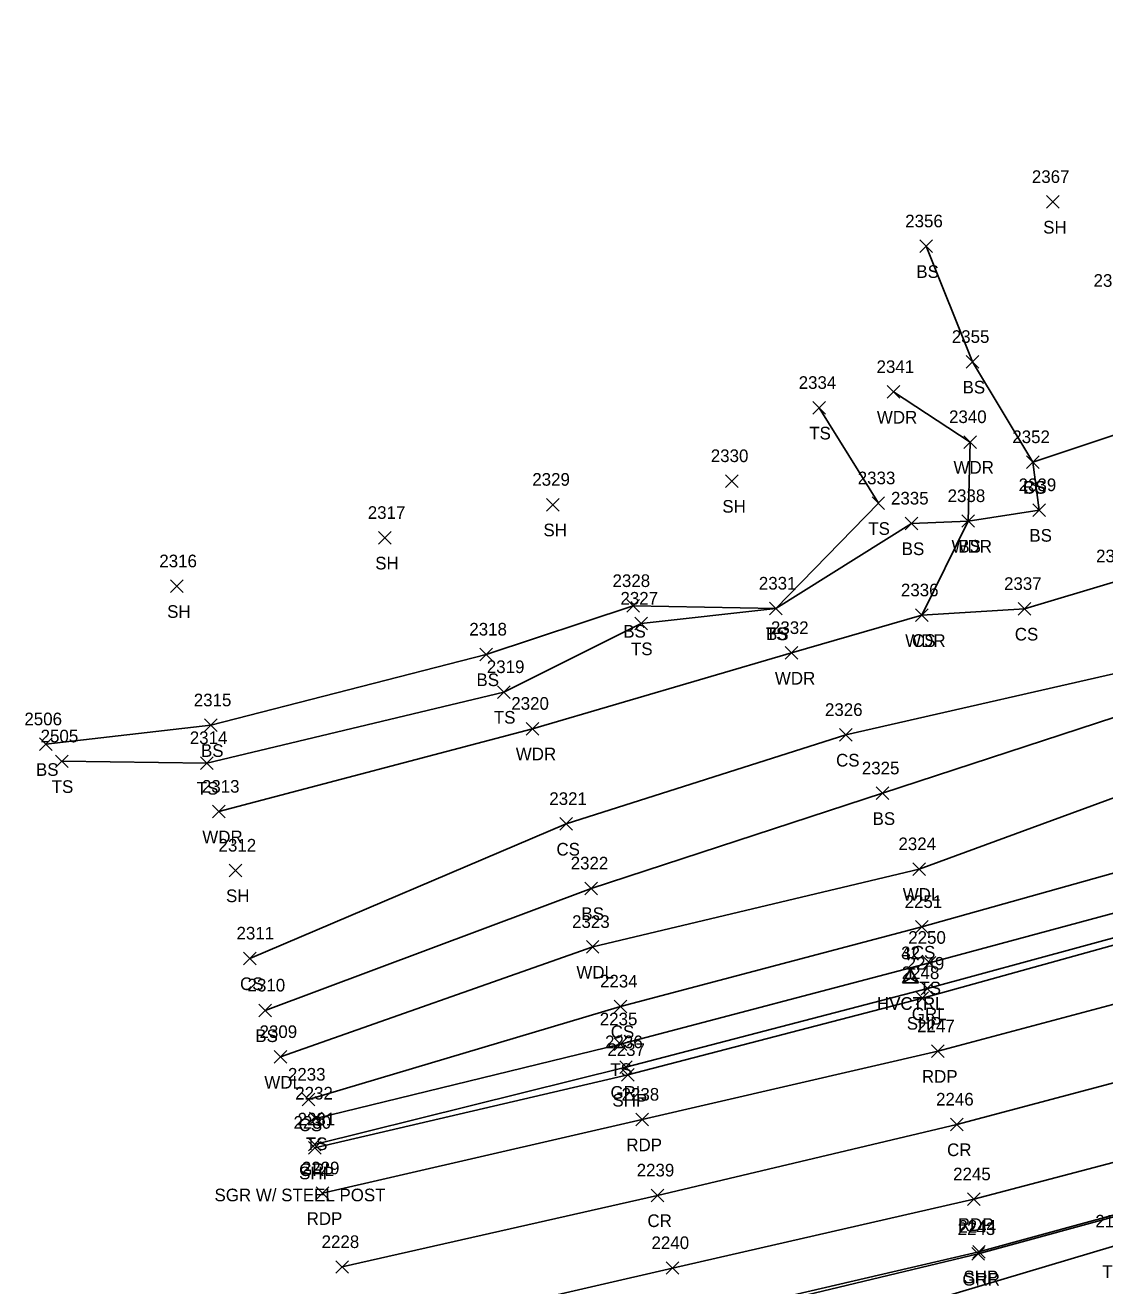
# Model space of a CAD drawing. Extents: x 1502194 to 1507887, y 142265 to 144150.
# Drawn here: x 1506482.3 to 1506653.1, y 143449.6 to 143648.9 of the extents above; entities that cross this region are included whole.
import ezdxf

# ---------------------------------------------------------------- set-up
doc = ezdxf.new("R2010")
doc.units = 0
for name, color, linetype in [('C_A', 7, 'Continuous'), ('C_I', 7, 'Continuous'), ('CPSM', 7, 'Continuous'), ('L_A', 7, 'Continuous'), ('L_I', 7, 'Continuous'), ('L_TIC', 7, 'Continuous'), ('LAWA', 7, 'Continuous'), ('LELB', 7, 'Continuous'), ('P_A', 7, 'Continuous'), ('P_I', 7, 'Continuous'), ('P_TIC', 7, 'Continuous'), ('PET', 7, 'Continuous'), ('PRC', 7, 'Continuous'), ('PSP', 7, 'Continuous'), ('R_A', 7, 'Continuous'), ('R_C', 7, 'Continuous'), ('R_I', 7, 'Continuous'), ('R_TIC', 7, 'Continuous'), ('RGR', 7, 'Continuous')]:
    doc.layers.add(name, color=color, linetype=linetype)

msp = doc.modelspace()

# ---------------------------------------------------------------- linework, layer by layer
at = {"layer": 'CPSM'}
for p, q in [((1506621.06, 143497.5), (1506622.31, 143499.66)), ((1506621.06, 143497.5), (1506622.31, 143498.22)), ((1506621.07, 143497.49), (1506622.32, 143499.66)), ((1506621.07, 143497.49), (1506622.32, 143498.21)), ((1506623.56, 143497.5), (1506622.31, 143499.66)), ((1506622.31, 143498.22), (1506622.31, 143499.66)), ((1506622.31, 143498.22), (1506622.31, 143498.22)), ((1506622.31, 143498.22), (1506623.56, 143497.5)), ((1506623.57, 143497.49), (1506622.32, 143499.66)), ((1506622.32, 143498.21), (1506622.32, 143499.66)), ((1506622.32, 143498.21), (1506622.32, 143498.21)), ((1506622.32, 143498.21), (1506623.57, 143497.49)), ((1506621.06, 143497.5), (1506623.56, 143497.5)), ((1506621.07, 143497.49), (1506623.57, 143497.49))]:
    msp.add_line(p, q, dxfattribs=at)
at = {"layer": 'L_TIC'}
for points in [[(1506643.82, 143620), (1506645.82, 143622)], [(1506645.82, 143620), (1506643.82, 143622)], [(1506623.81, 143612.98), (1506625.81, 143614.98)], [(1506625.81, 143612.98), (1506623.81, 143614.98)], [(1506631.12, 143594.7), (1506633.12, 143596.7)], [(1506633.12, 143594.7), (1506631.12, 143596.7)], [(1506618.65, 143589.94), (1506620.65, 143591.94)], [(1506620.65, 143589.94), (1506618.65, 143591.94)], [(1506606.9, 143587.43), (1506608.9, 143589.43)], [(1506608.9, 143587.43), (1506606.9, 143589.43)], [(1506630.77, 143582.02), (1506632.77, 143584.02)], [(1506632.77, 143582.02), (1506630.77, 143584.02)], [(1506640.69, 143578.85), (1506642.69, 143580.85)], [(1506642.69, 143578.85), (1506640.69, 143580.85)], [(1506640.69, 143578.85), (1506642.69, 143580.85)], [(1506642.69, 143578.85), (1506640.69, 143580.85)], [(1506593.09, 143575.85), (1506595.09, 143577.85)], [(1506595.09, 143575.85), (1506593.09, 143577.85)], [(1506564.78, 143572.11), (1506566.78, 143574.11)], [(1506566.78, 143572.11), (1506564.78, 143574.11)], [(1506616.24, 143572.34), (1506618.24, 143574.34)], [(1506618.24, 143572.34), (1506616.24, 143574.34)], [(1506630.46, 143569.53), (1506632.46, 143571.53)], [(1506632.46, 143569.53), (1506630.46, 143571.53)], [(1506630.46, 143569.53), (1506632.46, 143571.53)], [(1506632.46, 143569.53), (1506630.46, 143571.53)], [(1506641.69, 143571.26), (1506643.69, 143573.26)], [(1506643.69, 143571.26), (1506641.69, 143573.26)], [(1506621.5, 143569.14), (1506623.5, 143571.14)], [(1506623.5, 143569.14), (1506621.5, 143571.14)], [(1506538.18, 143566.87), (1506540.18, 143568.87)], [(1506540.18, 143566.87), (1506538.18, 143568.87)], [(1506505.27, 143559.21), (1506507.27, 143561.21)], [(1506507.27, 143559.21), (1506505.27, 143561.21)], [(1506577.46, 143556.09), (1506579.46, 143558.09)], [(1506579.46, 143556.09), (1506577.46, 143558.09)], [(1506600.03, 143555.69), (1506602.03, 143557.69)], [(1506602.03, 143555.69), (1506600.03, 143557.69)], [(1506600.03, 143555.69), (1506602.03, 143557.69)], [(1506602.03, 143555.69), (1506600.03, 143557.69)], [(1506639.38, 143555.63), (1506641.38, 143557.63)], [(1506641.38, 143555.63), (1506639.38, 143557.63)], [(1506623.13, 143554.62), (1506625.13, 143556.62)], [(1506625.13, 143554.62), (1506623.13, 143556.62)], [(1506623.13, 143554.62), (1506625.13, 143556.62)], [(1506625.13, 143554.62), (1506623.13, 143556.62)], [(1506578.71, 143553.31), (1506580.71, 143555.31)], [(1506580.71, 143553.31), (1506578.71, 143555.31)], [(1506554.24, 143548.42), (1506556.24, 143550.42)], [(1506556.24, 143548.42), (1506554.24, 143550.42)], [(1506602.52, 143548.66), (1506604.52, 143550.66)], [(1506604.52, 143548.66), (1506602.52, 143550.66)], [(1506557.02, 143542.48), (1506559.02, 143544.48)], [(1506559.02, 143542.48), (1506557.02, 143544.48)], [(1506510.67, 143537.22), (1506512.67, 143539.22)], [(1506512.67, 143537.22), (1506510.67, 143539.22)], [(1506561.54, 143536.68), (1506563.54, 143538.68)], [(1506563.54, 143536.68), (1506561.54, 143538.68)], [(1506611.11, 143535.7), (1506613.11, 143537.7)], [(1506613.11, 143535.7), (1506611.11, 143537.7)], [(1506484.57, 143534.22), (1506486.57, 143536.22)], [(1506486.57, 143534.22), (1506484.57, 143536.22)], [(1506487.09, 143531.52), (1506489.09, 143533.52)], [(1506489.09, 143531.52), (1506487.09, 143533.52)], [(1506510.03, 143531.25), (1506512.03, 143533.25)], [(1506512.03, 143531.25), (1506510.03, 143533.25)], [(1506616.89, 143526.46), (1506618.89, 143528.46)], [(1506618.89, 143526.46), (1506616.89, 143528.46)], [(1506511.95, 143523.56), (1506513.95, 143525.56)], [(1506513.95, 143523.56), (1506511.95, 143525.56)], [(1506566.89, 143521.62), (1506568.89, 143523.62)], [(1506568.89, 143521.62), (1506566.89, 143523.62)], [(1506514.58, 143514.25), (1506516.58, 143516.25)], [(1506516.58, 143514.25), (1506514.58, 143516.25)], [(1506622.68, 143514.47), (1506624.68, 143516.47)], [(1506624.68, 143514.47), (1506622.68, 143516.47)], [(1506570.84, 143511.42), (1506572.84, 143513.42)], [(1506572.84, 143511.42), (1506570.84, 143513.42)], [(1506623.1, 143505.32), (1506625.1, 143507.32)], [(1506625.1, 143505.32), (1506623.1, 143507.32)], [(1506571.06, 143502.17), (1506573.06, 143504.17)], [(1506573.06, 143502.17), (1506571.06, 143504.17)], [(1506516.85, 143500.34), (1506518.85, 143502.34)], [(1506518.85, 143500.34), (1506516.85, 143502.34)], [(1506624.32, 143499.66), (1506626.32, 143501.66)], [(1506626.32, 143499.66), (1506624.32, 143501.66)], [(1506519.26, 143492.12), (1506521.26, 143494.12)], [(1506521.26, 143492.12), (1506519.26, 143494.12)], [(1506575.48, 143492.75), (1506577.48, 143494.75)], [(1506577.48, 143492.75), (1506575.48, 143494.75)], [(1506575.44, 143486.76), (1506577.44, 143488.76)], [(1506577.44, 143486.76), (1506575.44, 143488.76)], [(1506521.71, 143484.76), (1506523.71, 143486.76)], [(1506523.71, 143484.76), (1506521.71, 143486.76)], [(1506526.12, 143478.02), (1506528.12, 143480.02)], [(1506528.12, 143478.02), (1506526.12, 143480.02)], [(1506527.28, 143475.03), (1506529.28, 143477.03)], [(1506529.28, 143475.03), (1506527.28, 143477.03)]]:
    msp.add_lwpolyline(points, dxfattribs=at)
at = {"layer": 'LAWA'}
for points in [[(1506522.71, 143485.76), (1506572.06, 143503.17), (1506623.68, 143515.47), (1506667.22, 143531.44), (1506692.19, 143539.75), (1506705.6, 143543.12), (1506724.44, 143544.97), (1506738.66, 143547.16), (1506749.81, 143546.64), (1506758.77, 143557.3), (1506807.57, 143579.94), (1506846.79, 143592.4), (1506896.99, 143614.38)], [(1506512.95, 143524.56), (1506562.54, 143537.68), (1506603.52, 143549.66), (1506624.13, 143555.62), (1506631.46, 143570.53), (1506631.77, 143583.02), (1506619.65, 143590.94)]]:
    msp.add_lwpolyline(points, dxfattribs=at)
at = {"layer": 'LELB'}
for points in [[(1506624.13, 143555.62), (1506640.38, 143556.63), (1506654.94, 143561), (1506672.72, 143565.79), (1506679.72, 143575.67), (1506695.05, 143577.62), (1506699.47, 143577.91), (1506701.5, 143575.19), (1506703.76, 143575.39), (1506707.13, 143577.97), (1506705.55, 143581.26), (1506716.61, 143587.23), (1506735.68, 143602.47), (1506756.62, 143603.39), (1506780.29, 143609.03), (1506830.83, 143625.99), (1506880.34, 143648.95)], [(1506517.85, 143501.34), (1506567.89, 143522.62), (1506612.11, 143536.7), (1506661.61, 143547.98), (1506681.76, 143559.52), (1506695.53, 143572.24), (1506704.85, 143572.91), (1506725.52, 143573.91), (1506746.5, 143587.18), (1506797.75, 143604.14), (1506837.79, 143614.31), (1506888.27, 143631.28)], [(1506511.67, 143538.22), (1506555.24, 143549.42), (1506578.46, 143557.09), (1506601.03, 143556.69), (1506622.5, 143570.14), (1506631.46, 143570.53), (1506642.69, 143572.26), (1506641.69, 143579.85), (1506632.12, 143595.7), (1506624.81, 143613.98)], [(1506520.26, 143493.12), (1506571.84, 143512.42), (1506617.89, 143527.46), (1506663.2, 143542.3), (1506684.6, 143550.02), (1506709.64, 143561.03), (1506743.74, 143569.88), (1506756.3, 143575.97), (1506802.67, 143594.79), (1506845.42, 143601.65), (1506896.99, 143614.38)], [(1506527.12, 143479.02), (1506576.48, 143493.75), (1506624.1, 143506.32), (1506671.3, 143519.58), (1506718.08, 143535.11), (1506766.47, 143551.82), (1506810.91, 143567.85), (1506852.21, 143584.27), (1506899, 143603.69)], [(1506528.28, 143476.03), (1506576.44, 143487.76), (1506625.32, 143500.66), (1506672.84, 143513.46), (1506720.65, 143528.12), (1506770.21, 143545.68), (1506814.12, 143560.53), (1506853.98, 143576.57), (1506901.25, 143597.01)], [(1506511.03, 143532.25), (1506558.02, 143543.48), (1506579.71, 143554.31), (1506601.03, 143556.69), (1506617.24, 143573.34), (1506607.9, 143588.43)], [(1506641.69, 143579.85), (1506662.54, 143586.81), (1506690.86, 143582.96)], [(1506920.49, 143550.15), (1506879.81, 143532.73), (1506832.93, 143512.84), (1506791.89, 143498.35), (1506750.34, 143484.06), (1506703.75, 143467.85), (1506654.25, 143455.79), (1506605.88, 143441.31), (1506565.5, 143431.73), (1506554.53, 143418.24), (1506550.8, 143411.14), (1506553.36, 143401.15), (1506568.06, 143393.58), (1506589.98, 143377.59)], [(1506485.57, 143535.22), (1506511.67, 143538.22)], [(1506488.09, 143532.52), (1506511.03, 143532.25)]]:
    msp.add_lwpolyline(points, dxfattribs=at)
at = {"layer": 'P_TIC'}
for points in [[(1506623.2, 143494.08), (1506625.2, 143496.08)], [(1506625.2, 143494.08), (1506623.2, 143496.08)], [(1506625.64, 143485.68), (1506627.64, 143487.68)], [(1506627.64, 143485.68), (1506625.64, 143487.68)], [(1506576.64, 143481.92), (1506578.64, 143483.92)], [(1506578.64, 143481.92), (1506576.64, 143483.92)], [(1506578.89, 143474.85), (1506580.89, 143476.85)], [(1506580.89, 143474.85), (1506578.89, 143476.85)], [(1506628.68, 143474.08), (1506630.68, 143476.08)], [(1506630.68, 143474.08), (1506628.68, 143476.08)], [(1506527.1, 143470.41), (1506529.1, 143472.41)], [(1506529.1, 143470.41), (1506527.1, 143472.41)], [(1506528.33, 143463.2), (1506530.33, 143465.2)], [(1506530.33, 143463.2), (1506528.33, 143465.2)], [(1506581.29, 143462.86), (1506583.29, 143464.86)], [(1506583.29, 143462.86), (1506581.29, 143464.86)], [(1506631.33, 143462.25), (1506633.33, 143464.25)], [(1506633.33, 143462.25), (1506631.33, 143464.25)], [(1506632.16, 143453.96), (1506634.16, 143455.96)], [(1506634.16, 143453.96), (1506632.16, 143455.96)], [(1506531.45, 143451.54), (1506533.45, 143453.54)], [(1506533.45, 143451.54), (1506531.45, 143453.54)], [(1506583.71, 143451.38), (1506585.71, 143453.38)], [(1506585.71, 143451.38), (1506583.71, 143453.38)]]:
    msp.add_lwpolyline(points, dxfattribs=at)
at = {"layer": 'PET'}
for points in [[(1506529.33, 143464.2), (1506579.89, 143475.85), (1506626.64, 143486.68), (1506676.46, 143499.95), (1506725.85, 143514.52), (1506772.5, 143530.8), (1506818.76, 143548.14), (1506859.25, 143564.41), (1506906.68, 143584.91)], [(1506536.88, 143441.34), (1506584.71, 143452.38), (1506632.33, 143463.25), (1506682.2, 143476.4), (1506730.21, 143490.72), (1506780.44, 143507.94), (1506828.66, 143525.9), (1506867.29, 143541.82), (1506915.31, 143562.43)]]:
    msp.add_lwpolyline(points, dxfattribs=at)
at = {"layer": 'PRC'}
msp.add_lwpolyline([(1506532.45, 143452.54), (1506582.29, 143463.86), (1506629.68, 143475.08), (1506679.65, 143488.39), (1506728.72, 143502.79), (1506776.57, 143519.3), (1506824.43, 143537.37), (1506862.78, 143553.15), (1506910.97, 143573.95)], dxfattribs=at)
at = {"layer": 'PSP'}
for points in [[(1506528.1, 143471.41), (1506577.64, 143482.92), (1506624.2, 143495.08), (1506674.01, 143508.85), (1506722.38, 143522.96), (1506769.18, 143539.06), (1506814.23, 143556.06), (1506856.23, 143573.29), (1506902.36, 143593.17)], [(1506542.57, 143434.01), (1506586.24, 143444.04), (1506633.16, 143454.96), (1506684.08, 143468.88), (1506730.5, 143482.95), (1506782.84, 143500.58), (1506831.22, 143518.57), (1506871.13, 143534.59), (1506917.52, 143554.61)]]:
    msp.add_lwpolyline(points, dxfattribs=at)
at = {"layer": 'R_TIC'}
for points in [[(1506623.99, 143495.57), (1506625.99, 143497.57)], [(1506625.99, 143495.57), (1506623.99, 143497.57)], [(1506576.33, 143483.15), (1506578.33, 143485.15)], [(1506578.33, 143483.15), (1506576.33, 143485.15)], [(1506527.09, 143470.93), (1506529.09, 143472.93)], [(1506529.09, 143470.93), (1506527.09, 143472.93)], [(1506632.04, 143453.6), (1506634.04, 143455.6)], [(1506634.04, 143453.6), (1506632.04, 143455.6)]]:
    msp.add_lwpolyline(points, dxfattribs=at)
at = {"layer": 'RGR'}
for points in [[(1506528.09, 143471.93), (1506577.33, 143484.15), (1506624.99, 143496.57), (1506673.85, 143509.85), (1506721.49, 143524.09), (1506768.89, 143540.23), (1506815.19, 143557.42), (1506856.11, 143574.12), (1506902.1, 143593.94)], [(1506543.48, 143429.76), (1506556.69, 143434.17), (1506568.66, 143438.23), (1506586.4, 143443.43), (1506633.04, 143454.6), (1506684.23, 143468.58), (1506730.71, 143482.6), (1506783.02, 143500.15), (1506831.56, 143518.03), (1506871.47, 143534.19), (1506917.7, 143554.27)]]:
    msp.add_lwpolyline(points, dxfattribs=at)

# ---------------------------------------------------------------- texts
at = {"layer": 'C_A'}
for p in [(1506617, 143493.22), (1506617.02, 143493.21)]:
    msp.add_text('HVCTRL', height=2, dxfattribs=at).set_placement(p)
at = {"layer": 'C_I'}
for s, p in [('42', (1506620.86, 143501.21)), ('32', (1506620.84, 143501.22))]:
    msp.add_text(s, height=2, dxfattribs=at).set_placement(p)
at = {"layer": 'L_A'}
for s, p in [('SH', (1506643.31, 143616)), ('BS', (1506623.25, 143608.98)), ('BS', (1506630.56, 143590.7)), ('WDR', (1506617.01, 143585.94)), ('TS', (1506606.31, 143583.43)), ('WDR', (1506629.13, 143578.02)), ('CS', (1506640.13, 143574.85)), ('BS', (1506640.13, 143574.85)), ('SH', (1506592.57, 143571.85)), ('SH', (1506564.27, 143568.11)), ('TS', (1506615.65, 143568.34)), ('WDR', (1506628.82, 143565.53)), ('BS', (1506629.9, 143565.53)), ('BS', (1506641.13, 143567.26)), ('BS', (1506620.94, 143565.14)), ('SH', (1506537.67, 143562.87)), ('SH', (1506504.76, 143555.21)), ('BS', (1506576.9, 143552.09)), ('TS', (1506599.44, 143551.69)), ('BS', (1506599.48, 143551.69)), ('CS', (1506638.82, 143551.63)), ('WDR', (1506621.49, 143550.62)), ('CS', (1506622.57, 143550.62)), ('TS', (1506578.12, 143549.31)), ('BS', (1506553.68, 143544.42)), ('WDR', (1506600.88, 143544.66)), ('TS', (1506556.43, 143538.48)), ('BS', (1506510.11, 143533.22)), ('WDR', (1506559.9, 143532.68)), ('CS', (1506610.55, 143531.7)), ('BS', (1506484.01, 143530.22)), ('TS', (1506486.5, 143527.52)), ('TS', (1506509.44, 143527.25)), ('BS', (1506616.33, 143522.46)), ('WDR', (1506510.32, 143519.56)), ('CS', (1506566.33, 143517.62)), ('SH', (1506514.07, 143510.25)), ('WDL', (1506621.1, 143510.47)), ('BS', (1506570.28, 143507.42)), ('CS', (1506622.54, 143501.32)), ('WDL', (1506569.48, 143498.17)), ('CS', (1506516.29, 143496.34)), ('TS', (1506623.73, 143495.66)), ('BS', (1506518.7, 143488.12)), ('CS', (1506574.92, 143488.75)), ('TS', (1506574.85, 143482.76)), ('WDL', (1506520.13, 143480.76)), ('CS', (1506525.56, 143474.02)), ('TS', (1506526.69, 143471.03)), ('TS', (1506652.66, 143450.79))]:
    msp.add_text(s, height=2, dxfattribs=at).set_placement(p)
at = {"layer": 'L_I'}
for s, p in [('2367', (1506641.52, 143624)), ('2356', (1506621.49, 143616.98)), ('2354', (1506651.28, 143607.57)), ('2355', (1506628.86, 143598.7)), ('2341', (1506616.96, 143593.94)), ('2334', (1506604.64, 143591.43)), ('2340', (1506628.42, 143586.02)), ('2352', (1506638.43, 143582.85)), ('2352', (1506638.43, 143582.85)), ('2330', (1506590.74, 143579.85)), ('2329', (1506562.51, 143576.11)), ('2333', (1506613.98, 143576.34)), ('2338', (1506628.2, 143573.53)), ('2338', (1506628.2, 143573.53)), ('2339', (1506639.43, 143575.26)), ('2335', (1506619.24, 143573.14)), ('2317', (1506536.49, 143570.87)), ('2342', (1506651.68, 143564)), ('2316', (1506503.52, 143563.21)), ('2328', (1506575.2, 143560.09)), ('2331', (1506598.34, 143559.69)), ('2331', (1506598.34, 143559.69)), ('2337', (1506637.12, 143559.63)), ('2336', (1506620.81, 143558.62)), ('2336', (1506620.81, 143558.62)), ('2327', (1506576.45, 143557.31)), ('2318', (1506552.55, 143552.42)), ('2332', (1506600.26, 143552.66)), ('2319', (1506555.32, 143546.48)), ('2315', (1506508.97, 143541.22)), ('2320', (1506559.19, 143540.68)), ('2326', (1506608.8, 143539.7)), ('2506', (1506482.18, 143538.22)), ('2505', (1506484.75, 143535.52)), ('2314', (1506508.34, 143535.25)), ('2325', (1506614.63, 143530.46)), ('2313', (1506510.26, 143527.56)), ('2321', (1506565.2, 143525.62)), ('2312', (1506512.89, 143518.25)), ('2324', (1506620.42, 143518.47)), ('2322', (1506568.58, 143515.42)), ('2251', (1506621.4, 143509.32)), ('2323', (1506568.8, 143506.17)), ('2311', (1506515.73, 143504.34)), ('2250', (1506621.97, 143503.66)), ('2310', (1506517.48, 143496.12)), ('2234', (1506573.22, 143496.75)), ('2235', (1506573.18, 143490.76)), ('2309', (1506519.37, 143488.76)), ('2233', (1506523.86, 143482.02)), ('2232', (1506525.02, 143479.03)), ('2192', (1506651.56, 143458.79))]:
    msp.add_text(s, height=2, dxfattribs=at).set_placement(p)
at = {"layer": 'P_A'}
for s, p in [('SHP', (1506621.74, 143490.08)), ('RDP', (1506624.13, 143481.68)), ('SHP', (1506575.18, 143477.92)), ('RDP', (1506577.38, 143470.85)), ('CR', (1506628.11, 143470.08)), ('SHP', (1506525.63, 143466.41)), ('RDP', (1506526.82, 143459.2)), ('CR', (1506580.72, 143458.86)), ('RDP', (1506629.82, 143458.25)), ('SHP', (1506630.7, 143449.96))]:
    msp.add_text(s, height=2, dxfattribs=at).set_placement(p)
at = {"layer": 'P_I'}
for s, p in [('2248', (1506620.94, 143498.08)), ('2247', (1506623.38, 143489.68)), ('2237', (1506574.38, 143485.92)), ('2238', (1506576.63, 143478.85)), ('2246', (1506626.37, 143478.08)), ('2230', (1506524.75, 143474.41)), ('2229', (1506526.06, 143467.2)), ('2239', (1506579.02, 143466.86)), ('2245', (1506629.07, 143466.25)), ('2244', (1506629.9, 143457.96)), ('2228', (1506529.19, 143455.54)), ('2240', (1506581.37, 143455.38))]:
    msp.add_text(s, height=2, dxfattribs=at).set_placement(p)
at = {"layer": 'R_A'}
for s, p in [('GRL', (1506622.53, 143491.57)), ('GRL', (1506574.88, 143479.15)), ('GRL', (1506525.63, 143466.93)), ('GRR', (1506630.53, 143449.6))]:
    msp.add_text(s, height=2, dxfattribs=at).set_placement(p)
at = {"layer": 'R_C'}
msp.add_text('SGR W/ STEEL POST', height=2, dxfattribs=at).set_placement((1506512.25, 143462.93))
at = {"layer": 'R_I'}
for s, p in [('2249', (1506621.72, 143499.57)), ('2236', (1506574.02, 143487.15)), ('2231', (1506525.39, 143474.93)), ('2243', (1506629.78, 143457.6))]:
    msp.add_text(s, height=2, dxfattribs=at).set_placement(p)

doc.saveas('drawing.dxf')
